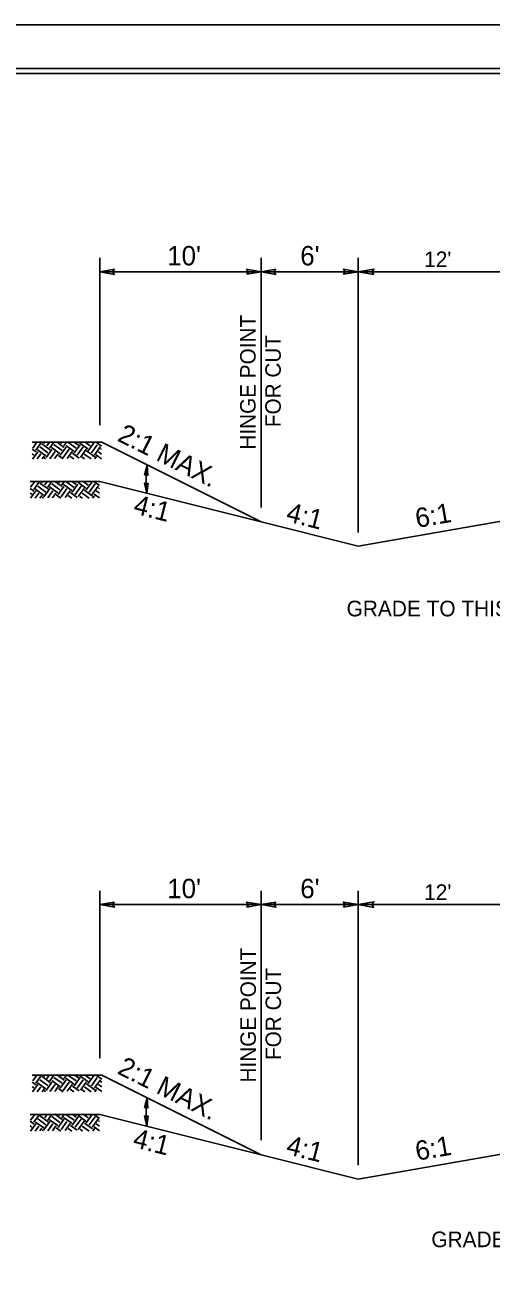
# Model space of a CAD drawing. Extents: x 3025871 to 3026431, y 707165 to 707825.
# Drawn here: x 3026107.4 to 3026143.5, y 707465.6 to 707562.1 of the extents above; entities that cross this region are included whole.
import ezdxf

# ---------------------------------------------------------------- set-up
doc = ezdxf.new("R2010")
doc.units = 0
for name, color, linetype in [('Old_Level_39', 7, 'Continuous'), ('Prop Drainage Structure Junction Box with Slab Lid TB 840 34 CELL', 7, 'Continuous'), ('Sheet Cutting Line CELL', 7, 'Continuous'), ('Typical Guardrail CELL', 7, 'Continuous'), ('Typical Shoulder Slope CELL', 7, 'Continuous'), ('Typical Terminator CELL', 7, 'Continuous'), ('Typical Text Centerline CELL', 7, 'Continuous'), ('Typical Text Grade Point CELL', 7, 'Continuous')]:
    doc.layers.add(name, color=color, linetype=linetype)

msp = doc.modelspace()

# ---------------------------------------------------------------- linework, layer by layer
at = {"layer": 'Old_Level_39'}
msp.add_lwpolyline([(3026273.948, 707558.686), (3026023.973, 707558.686), (3026023.973, 707400.421), (3026273.948, 707400.421)], close=True, dxfattribs=at)
at = {"layer": 'Prop Drainage Structure Junction Box with Slab Lid TB 840 34 CELL'}
for p, q in [((3026133.221, 707522.759), (3026133.221, 707544.01)), ((3026145.221, 707542.937), (3026133.221, 707542.937)), ((3026133.223, 707473.764), (3026133.223, 707495.015)), ((3026145.223, 707493.942), (3026133.223, 707493.942))]:
    msp.add_line(p, q, dxfattribs=at)
for centre in [(3026122.921, 707527.022), (3026122.922, 707478.039)]:
    msp.add_arc(centre, 6.116, 171.02532, 187.92933, dxfattribs=at)
at = {"layer": 'Sheet Cutting Line CELL'}
msp.add_lwpolyline([(3026272.073, 707558.304), (3026047.073, 707558.304), (3026047.073, 707400.804), (3026272.073, 707400.804)], close=True, dxfattribs=at)
at = {"layer": 'Typical Guardrail CELL'}
for p, q in [((3026113.38, 707529.74), (3026125.722, 707523.569)), ((3026113.216, 707526.701), (3026125.722, 707523.569)), ((3026125.722, 707523.569), (3026133.221, 707521.695)), ((3026113.382, 707480.745), (3026125.724, 707474.574)), ((3026113.218, 707477.706), (3026125.724, 707474.574)), ((3026125.724, 707474.574), (3026133.223, 707472.699))]:
    msp.add_line(p, q, dxfattribs=at)
at = {"layer": 'Typical Shoulder Slope CELL'}
for p, q in [((3026113.221, 707531.063), (3026113.221, 707544.01)), ((3026125.721, 707524.696), (3026125.721, 707544.01)), ((3026125.721, 707542.937), (3026113.221, 707542.937)), ((3026133.221, 707542.937), (3026125.721, 707542.937)), ((3026113.223, 707482.067), (3026113.223, 707495.015)), ((3026125.723, 707475.701), (3026125.723, 707495.015)), ((3026125.723, 707493.942), (3026113.223, 707493.942)), ((3026133.223, 707493.942), (3026125.723, 707493.942))]:
    msp.add_line(p, q, dxfattribs=at)
at = {"layer": 'Typical Terminator CELL'}
msp.add_lwpolyline([(3026274.623, 707562.054), (3026022.023, 707562.054), (3026022.023, 707397.054), (3026274.623, 707397.054)], close=True, dxfattribs=at)
at = {"layer": 'Typical Text Centerline CELL'}
for points in [[(3026114.346, 707543.131), (3026113.221, 707542.937), (3026114.352, 707542.737), (3026114.208, 707542.937)], [(3026124.596, 707542.744), (3026125.721, 707542.937), (3026124.59, 707543.137), (3026124.733, 707542.937)], [(3026126.846, 707543.131), (3026125.721, 707542.937), (3026126.852, 707542.737), (3026126.708, 707542.937)], [(3026132.096, 707542.744), (3026133.221, 707542.937), (3026132.09, 707543.137), (3026132.233, 707542.937)], [(3026134.446, 707542.726), (3026133.221, 707542.937), (3026134.453, 707543.155), (3026134.296, 707542.937)], [(3026116.667, 707527.204), (3026116.88, 707527.976), (3026116.942, 707527.172), (3026116.812, 707527.286)], [(3026116.959, 707526.584), (3026116.864, 707525.788), (3026116.683, 707526.574), (3026116.829, 707526.48)], [(3026114.348, 707494.136), (3026113.223, 707493.942), (3026114.354, 707493.742), (3026114.21, 707493.942)], [(3026124.598, 707493.748), (3026125.723, 707493.942), (3026124.591, 707494.142), (3026124.735, 707493.942)], [(3026126.848, 707494.136), (3026125.723, 707493.942), (3026126.854, 707493.742), (3026126.71, 707493.942)], [(3026132.098, 707493.748), (3026133.223, 707493.942), (3026132.091, 707494.142), (3026132.235, 707493.942)], [(3026134.448, 707493.731), (3026133.223, 707493.942), (3026134.454, 707494.16), (3026134.298, 707493.942)], [(3026116.669, 707478.22), (3026116.882, 707478.993), (3026116.944, 707478.188), (3026116.814, 707478.303)], [(3026116.961, 707477.6), (3026116.865, 707476.804), (3026116.685, 707477.59), (3026116.83, 707477.496)]]:
    msp.add_lwpolyline(points, close=True, dxfattribs=at)
at = {"layer": 'Typical Text Grade Point CELL'}
for p, q in [((3026113.38, 707529.74), (3026107.983, 707529.74)), ((3026108.282, 707528.987), (3026107.983, 707529.201)), ((3026108.021, 707529.294), (3026108.342, 707529.74)), ((3026108.259, 707529.123), (3026108.703, 707529.74)), ((3026109.201, 707528.927), (3026108.567, 707529.383)), ((3026109.372, 707529.165), (3026108.738, 707529.621)), ((3026108.874, 707529.644), (3026108.943, 707529.74)), ((3026109.053, 707528.553), (3026109.509, 707529.188)), ((3026109.112, 707529.473), (3026109.312, 707529.751)), ((3026109.35, 707529.302), (3026109.665, 707529.74)), ((3026110.121, 707528.868), (3026109.486, 707529.324)), ((3026110.292, 707529.106), (3026109.657, 707529.562)), ((3026110.463, 707529.344), (3026109.898, 707529.75)), ((3026110.143, 707528.731), (3026110.599, 707529.366)), ((3026110.203, 707529.651), (3026110.273, 707529.749)), ((3026110.381, 707528.56), (3026110.837, 707529.195)), ((3026110.441, 707529.48), (3026110.633, 707529.748)), ((3026111.212, 707529.046), (3026110.577, 707529.502)), ((3026111.383, 707529.284), (3026110.748, 707529.74)), ((3026111.234, 707528.91), (3026111.69, 707529.545)), ((3026111.554, 707529.522), (3026111.243, 707529.746)), ((3026111.472, 707528.739), (3026111.928, 707529.374)), ((3026111.531, 707529.659), (3026111.593, 707529.745)), ((3026112.302, 707529.225), (3026111.668, 707529.681)), ((3026111.71, 707528.568), (3026112.166, 707529.203)), ((3026112.473, 707529.463), (3026112.083, 707529.744)), ((3026112.325, 707529.089), (3026112.781, 707529.723)), ((3026112.563, 707528.918), (3026113.019, 707529.552)), ((3026112.644, 707529.701), (3026112.587, 707529.742)), ((3026112.801, 707528.747), (3026113.257, 707529.381)), ((3026113.36, 707529.427), (3026112.923, 707529.741)), ((3026113.36, 707529.187), (3026113.279, 707529.245)), ((3026108.111, 707528.749), (3026107.983, 707528.84)), ((3026108.01, 707528.441), (3026108.418, 707529.009)), ((3026108.376, 707528.448), (3026108.656, 707528.838)), ((3026109.03, 707528.689), (3026108.396, 707529.145)), ((3026108.742, 707528.455), (3026108.894, 707528.667)), ((3026109.013, 707528.461), (3026108.916, 707528.531)), ((3026109.352, 707528.468), (3026109.747, 707529.017)), ((3026109.718, 707528.475), (3026109.985, 707528.846)), ((3026110.369, 707528.449), (3026110.007, 707528.709)), ((3026110.695, 707528.495), (3026111.075, 707529.024)), ((3026111.206, 707528.449), (3026110.927, 707528.65)), ((3026111.619, 707528.513), (3026111.098, 707528.888)), ((3026112.043, 707528.449), (3026111.846, 707528.59)), ((3026112.545, 707528.449), (3026112.017, 707528.828)), ((3026112.823, 707528.61), (3026112.188, 707529.066)), ((3026112.827, 707528.449), (3026112.959, 707528.633)), ((3026113.36, 707528.465), (3026112.937, 707528.769)), ((3026113.36, 707528.826), (3026113.108, 707529.007)), ((3026113.216, 707526.701), (3026107.819, 707526.701)), ((3026107.857, 707526.255), (3026108.178, 707526.701)), ((3026108.095, 707526.084), (3026108.539, 707526.701)), ((3026109.037, 707525.888), (3026108.403, 707526.344)), ((3026109.208, 707526.126), (3026108.574, 707526.582)), ((3026108.71, 707526.605), (3026108.779, 707526.701)), ((3026108.948, 707526.434), (3026109.149, 707526.713)), ((3026109.186, 707526.263), (3026109.501, 707526.701)), ((3026109.957, 707525.829), (3026109.322, 707526.285)), ((3026110.128, 707526.067), (3026109.493, 707526.523)), ((3026110.299, 707526.305), (3026109.734, 707526.711)), ((3026109.979, 707525.693), (3026110.435, 707526.327)), ((3026110.039, 707526.612), (3026110.109, 707526.71)), ((3026110.277, 707526.441), (3026110.469, 707526.709)), ((3026111.048, 707526.007), (3026110.413, 707526.464)), ((3026111.219, 707526.245), (3026110.584, 707526.702)), ((3026111.07, 707525.871), (3026111.526, 707526.506)), ((3026111.39, 707526.483), (3026111.079, 707526.707)), ((3026111.308, 707525.7), (3026111.764, 707526.335)), ((3026111.367, 707526.62), (3026111.429, 707526.706)), ((3026112.138, 707526.186), (3026111.504, 707526.642)), ((3026112.309, 707526.424), (3026111.919, 707526.705)), ((3026112.161, 707526.05), (3026112.617, 707526.684)), ((3026112.399, 707525.879), (3026112.855, 707526.513)), ((3026112.48, 707526.662), (3026112.423, 707526.703)), ((3026112.637, 707525.708), (3026113.093, 707526.342)), ((3026113.196, 707526.388), (3026112.759, 707526.702)), ((3026108.118, 707525.948), (3026107.819, 707526.162)), ((3026107.947, 707525.71), (3026107.819, 707525.801)), ((3026107.846, 707525.402), (3026108.254, 707525.97)), ((3026108.212, 707525.409), (3026108.492, 707525.799)), ((3026108.866, 707525.65), (3026108.232, 707526.106)), ((3026108.578, 707525.417), (3026108.73, 707525.628)), ((3026108.849, 707525.422), (3026108.752, 707525.492)), ((3026108.889, 707525.514), (3026109.345, 707526.149)), ((3026109.188, 707525.429), (3026109.583, 707525.978)), ((3026109.554, 707525.436), (3026109.821, 707525.807)), ((3026110.205, 707525.41), (3026109.843, 707525.67)), ((3026110.217, 707525.522), (3026110.673, 707526.156)), ((3026110.531, 707525.456), (3026110.911, 707525.985)), ((3026111.042, 707525.41), (3026110.763, 707525.611)), ((3026111.455, 707525.474), (3026110.934, 707525.849)), ((3026111.546, 707525.529), (3026112.002, 707526.164)), ((3026111.879, 707525.41), (3026111.682, 707525.551)), ((3026112.382, 707525.41), (3026111.853, 707525.789)), ((3026112.659, 707525.571), (3026112.024, 707526.027)), ((3026112.663, 707525.41), (3026112.795, 707525.594)), ((3026113.196, 707525.426), (3026112.773, 707525.73)), ((3026113.196, 707525.787), (3026112.944, 707525.968)), ((3026113.196, 707526.148), (3026113.115, 707526.206)), ((3026145.221, 707523.785), (3026133.221, 707521.695)), ((3026113.382, 707480.745), (3026107.985, 707480.745)), ((3026108.283, 707479.991), (3026107.985, 707480.206)), ((3026108.011, 707479.445), (3026108.42, 707480.013)), ((3026108.023, 707480.299), (3026108.344, 707480.745)), ((3026108.261, 707480.128), (3026108.704, 707480.745)), ((3026109.032, 707479.694), (3026108.397, 707480.15)), ((3026109.203, 707479.932), (3026108.568, 707480.388)), ((3026109.374, 707480.17), (3026108.739, 707480.626)), ((3026108.876, 707480.648), (3026108.945, 707480.745)), ((3026109.054, 707479.557), (3026109.51, 707480.192)), ((3026109.114, 707480.477), (3026109.314, 707480.756)), ((3026109.352, 707480.306), (3026109.667, 707480.745)), ((3026109.354, 707479.472), (3026109.748, 707480.021)), ((3026110.123, 707479.872), (3026109.488, 707480.328)), ((3026110.294, 707480.11), (3026109.659, 707480.566)), ((3026110.465, 707480.348), (3026109.9, 707480.754)), ((3026110.145, 707479.736), (3026110.601, 707480.371)), ((3026110.204, 707480.656), (3026110.274, 707480.753)), ((3026110.383, 707479.565), (3026110.839, 707480.2)), ((3026110.442, 707480.485), (3026110.635, 707480.752)), ((3026111.213, 707480.051), (3026110.579, 707480.507)), ((3026110.696, 707479.499), (3026111.077, 707480.029)), ((3026111.384, 707480.289), (3026110.75, 707480.745)), ((3026111.236, 707479.915), (3026111.692, 707480.549)), ((3026111.555, 707480.527), (3026111.244, 707480.75)), ((3026111.474, 707479.744), (3026111.93, 707480.378)), ((3026111.533, 707480.663), (3026111.595, 707480.749)), ((3026112.304, 707480.229), (3026111.669, 707480.686)), ((3026111.712, 707479.573), (3026112.168, 707480.207)), ((3026112.475, 707480.467), (3026112.085, 707480.748)), ((3026112.825, 707479.615), (3026112.19, 707480.071)), ((3026112.326, 707480.093), (3026112.782, 707480.728)), ((3026112.564, 707479.922), (3026113.02, 707480.557)), ((3026112.646, 707480.705), (3026112.589, 707480.747)), ((3026112.802, 707479.751), (3026113.258, 707480.386)), ((3026113.361, 707480.432), (3026112.925, 707480.746)), ((3026113.361, 707479.83), (3026113.11, 707480.011)), ((3026113.361, 707480.191), (3026113.281, 707480.249)), ((3026108.112, 707479.753), (3026107.985, 707479.845)), ((3026108.377, 707479.453), (3026108.658, 707479.842)), ((3026108.744, 707479.46), (3026108.896, 707479.671)), ((3026109.015, 707479.465), (3026108.918, 707479.535)), ((3026109.72, 707479.48), (3026109.986, 707479.85)), ((3026110.371, 707479.453), (3026110.009, 707479.714)), ((3026111.208, 707479.453), (3026110.928, 707479.654)), ((3026111.62, 707479.518), (3026111.099, 707479.892)), ((3026112.045, 707479.453), (3026111.848, 707479.595)), ((3026112.547, 707479.453), (3026112.019, 707479.833)), ((3026112.829, 707479.453), (3026112.961, 707479.637)), ((3026113.361, 707479.47), (3026112.939, 707479.773)), ((3026113.218, 707477.706), (3026107.821, 707477.706)), ((3026108.119, 707476.952), (3026107.821, 707477.167)), ((3026107.859, 707477.26), (3026108.18, 707477.706)), ((3026108.097, 707477.089), (3026108.541, 707477.706)), ((3026108.868, 707476.655), (3026108.233, 707477.111)), ((3026109.039, 707476.893), (3026108.404, 707477.349)), ((3026109.21, 707477.131), (3026108.575, 707477.587)), ((3026108.712, 707477.609), (3026108.781, 707477.706)), ((3026108.89, 707476.519), (3026109.346, 707477.153)), ((3026108.95, 707477.438), (3026109.15, 707477.717)), ((3026109.188, 707477.267), (3026109.503, 707477.706)), ((3026109.959, 707476.833), (3026109.324, 707477.289)), ((3026110.13, 707477.071), (3026109.495, 707477.527)), ((3026110.301, 707477.309), (3026109.736, 707477.715)), ((3026109.981, 707476.697), (3026110.437, 707477.332)), ((3026110.04, 707477.617), (3026110.111, 707477.714)), ((3026110.219, 707476.526), (3026110.675, 707477.161)), ((3026110.278, 707477.446), (3026110.471, 707477.713)), ((3026111.049, 707477.012), (3026110.415, 707477.468)), ((3026111.22, 707477.25), (3026110.586, 707477.706)), ((3026111.072, 707476.876), (3026111.528, 707477.51)), ((3026111.391, 707477.488), (3026111.08, 707477.712)), ((3026111.31, 707476.705), (3026111.766, 707477.339)), ((3026111.369, 707477.624), (3026111.431, 707477.711)), ((3026112.14, 707477.191), (3026111.505, 707477.647)), ((3026111.548, 707476.534), (3026112.004, 707477.168)), ((3026112.311, 707477.429), (3026111.921, 707477.709)), ((3026112.162, 707477.054), (3026112.618, 707477.689)), ((3026112.4, 707476.883), (3026112.856, 707477.518)), ((3026112.482, 707477.667), (3026112.425, 707477.708)), ((3026112.638, 707476.712), (3026113.094, 707477.347)), ((3026113.198, 707477.393), (3026112.761, 707477.707)), ((3026113.198, 707477.152), (3026113.117, 707477.21)), ((3026107.948, 707476.714), (3026107.821, 707476.806)), ((3026107.847, 707476.406), (3026108.256, 707476.975)), ((3026108.214, 707476.414), (3026108.494, 707476.804)), ((3026108.58, 707476.421), (3026108.732, 707476.633)), ((3026108.851, 707476.426), (3026108.754, 707476.496)), ((3026109.19, 707476.433), (3026109.584, 707476.982)), ((3026109.556, 707476.441), (3026109.822, 707476.811)), ((3026110.207, 707476.414), (3026109.845, 707476.675)), ((3026110.533, 707476.46), (3026110.913, 707476.99)), ((3026111.044, 707476.414), (3026110.764, 707476.615)), ((3026111.457, 707476.479), (3026110.935, 707476.853)), ((3026111.881, 707476.414), (3026111.684, 707476.556)), ((3026112.383, 707476.414), (3026111.855, 707476.794)), ((3026112.661, 707476.576), (3026112.026, 707477.032)), ((3026112.665, 707476.414), (3026112.797, 707476.598)), ((3026113.198, 707476.431), (3026112.775, 707476.734)), ((3026113.198, 707476.792), (3026112.946, 707476.972)), ((3026145.223, 707474.79), (3026133.223, 707472.699))]:
    msp.add_line(p, q, dxfattribs=at)

# ---------------------------------------------------------------- texts
at = {"layer": 'Prop Drainage Structure Junction Box with Slab Lid TB 840 34 CELL'}
for s, height, p in [("12'", 1.2089, (3026138.342, 707543.299)), ('GRADE TO THIS LINE', 1.20892, (3026132.334, 707516.263)), ("12'", 1.2089, (3026138.344, 707494.303)), ('GRADE TO THIS LINE', 1.20892, (3026138.899, 707467.423))]:
    msp.add_text(s, height=height, dxfattribs=at).set_placement(p)
at = {"layer": 'Typical Guardrail CELL'}
for s, rotation, p in [('2:1 MAX.', 333.43495, (3026114.495, 707529.889)), ('4:1', 345.96376, (3026115.75, 707524.243)), ('4:1', 345.96376, (3026127.573, 707523.65)), ('2:1 MAX.', 333.43495, (3026114.497, 707480.893)), ('4:1', 345.96376, (3026115.702, 707475.192)), ('4:1', 345.96376, (3026127.575, 707474.655))]:
    msp.add_text(s, height=1.5, rotation=rotation, dxfattribs=at).set_placement(p)
at = {"layer": 'Typical Shoulder Slope CELL'}
for s, p in [("10' ", (3026118.438, 707543.437)), ("6' ", (3026128.744, 707543.437)), ("10' ", (3026118.44, 707494.442)), ("6' ", (3026128.745, 707494.442))]:
    msp.add_text(s, height=1.5, dxfattribs=at).set_placement(p)
for s, p in [('HINGE POINT', (3026125.287, 707529.17)), ('FOR CUT', (3026127.237, 707530.911)), ('HINGE POINT', (3026125.308, 707480.174)), ('FOR CUT', (3026127.258, 707481.915))]:
    msp.add_text(s, height=1.2, rotation=90, dxfattribs=at).set_placement(p)
at = {"layer": 'Typical Text Grade Point CELL'}
for p in [(3026137.793, 707523.105), (3026137.794, 707474.11)]:
    msp.add_text('6:1', height=1.5, rotation=9.88364, dxfattribs=at).set_placement(p)

doc.saveas('drawing.dxf')
